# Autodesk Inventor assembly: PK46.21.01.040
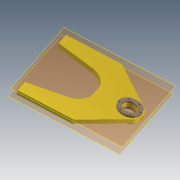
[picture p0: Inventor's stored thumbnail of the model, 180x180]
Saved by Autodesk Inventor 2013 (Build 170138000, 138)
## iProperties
Created: 2005-04
Part Number: PK46.21.01.040
Document SubType Name: Assembly
Designer: salex
Manufacturer: Standard
Standards Organization: Custom
Author: salex
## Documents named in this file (3)
- C:\Product Design Suite 2013\Data\Assy, Chassis, Front\PK46.21.01.040.iam
- C:\Product Design Suite 2013\Data\Assy, Chassis, Front\PK46.21.01.008.ipt
- C:\Product Design Suite 2013\Data\Assy, Chassis, Front\PK46.21.01.009.ipt
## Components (3 placed, 2 different names)
1. PK46.21.01.008:1 — Insert:1, Insert:2, Flush:1
2. PK46.21.01.009:1 — Insert:1
3. PK46.21.01.009:2 — Insert:2
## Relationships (3: Insert 2, Flush 1)
- Insert:1: PK46.21.01.008:1 ↔ PK46.21.01.009:1
- Insert:2: PK46.21.01.008:1 ↔ PK46.21.01.009:2
- Flush:1: PK46.21.01.008:1
